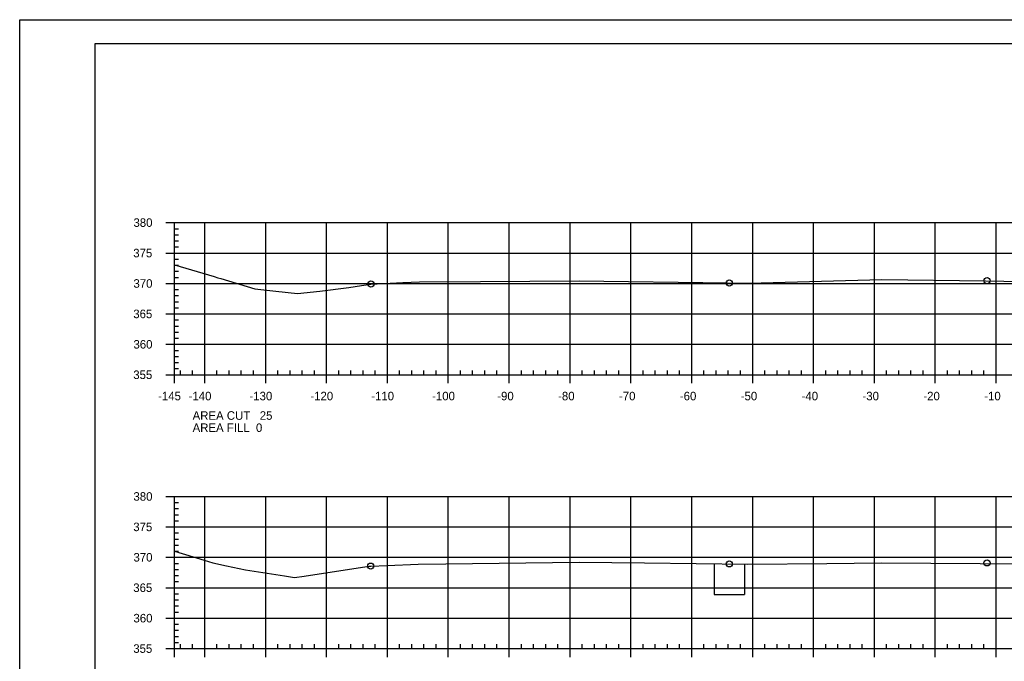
# Model space of a CAD drawing. Extents: x 1359801 to 1362404, y 372415 to 374228.
# Drawn here: x 1360417.1 to 1360578.9, y 373695.8 to 373801.3 of the extents above; entities that cross this region are included whole.
import ezdxf

# ---------------------------------------------------------------- set-up
doc = ezdxf.new("R2010")
doc.units = 0
for name, color, linetype in [('S_DRG_PT_SYM', 7, 'Continuous'), ('S_MAILBOX', 7, 'Continuous'), ('S_PRIMARY_CTL', 7, 'Continuous'), ('S_SHOULDER', 7, 'Continuous'), ('S_UTILITY_POLE_ANNOT', 7, 'Continuous'), ('S_UTL_PT_SYM', 7, 'Continuous'), ('S_WATER_UTILITIES', 7, 'Continuous')]:
    doc.layers.add(name, color=color, linetype=linetype)

msp = doc.modelspace()

# ---------------------------------------------------------------- linework, layer by layer
at = {"layer": 'S_DRG_PT_SYM'}
for points in [[(1360442.53, 373760.99), (1360449.09, 373759.06), (1360449.67, 373758.89), (1360450.14, 373758.75), (1360455.76, 373757.05), (1360459.18, 373756.69), (1360462.78, 373756.29), (1360466.4, 373756.67), (1360471.17, 373757.27), (1360473.27, 373757.6), (1360474.82, 373757.85), (1360480.08, 373758.08), (1360482.79, 373758.2), (1360492.83, 373758.27), (1360509.02, 373758.38), (1360533.39, 373758.02), (1360536.78, 373757.97), (1360538.91, 373758.03), (1360558.72, 373758.6), (1360575.78, 373758.36), (1360584.86, 373758.23)], [(1360442.53, 373713.97), (1360447.4, 373712.49), (1360448.84, 373712.04), (1360451.11, 373711.56), (1360454.2, 373710.87), (1360460.61, 373709.87), (1360462.26, 373709.61), (1360463.85, 373709.86), (1360471.31, 373711), (1360474.52, 373711.46), (1360474.8, 373711.5), (1360477.49, 373711.61), (1360482.57, 373711.82), (1360487.1, 373711.88), (1360509.01, 373712.14), (1360519.76, 373712.02), (1360536.71, 373711.82), (1360549.71, 373711.92), (1360558.67, 373712.03), (1360574.88, 373711.91), (1360584.99, 373711.84)]]:
    msp.add_lwpolyline(points, dxfattribs=at)
at = {"layer": 'S_MAILBOX'}
for p, q in [((1360442.53, 373767.94), (1360732.53, 373767.94)), ((1360442.53, 373742.94), (1360442.53, 373767.94)), ((1360447.53, 373742.94), (1360447.53, 373767.94)), ((1360457.53, 373742.94), (1360457.53, 373767.94)), ((1360467.53, 373742.94), (1360467.53, 373767.94)), ((1360477.53, 373742.94), (1360477.53, 373767.94)), ((1360487.53, 373742.94), (1360487.53, 373767.94)), ((1360497.53, 373742.94), (1360497.53, 373767.94)), ((1360507.53, 373742.94), (1360507.53, 373767.94)), ((1360517.53, 373742.94), (1360517.53, 373767.94)), ((1360527.53, 373742.94), (1360527.53, 373767.94)), ((1360537.53, 373742.94), (1360537.53, 373767.94)), ((1360547.53, 373742.94), (1360547.53, 373767.94)), ((1360557.53, 373742.94), (1360557.53, 373767.94)), ((1360567.53, 373742.94), (1360567.53, 373767.94)), ((1360577.53, 373742.94), (1360577.53, 373767.94)), ((1360442.53, 373762.94), (1360732.53, 373762.94)), ((1360442.53, 373757.94), (1360732.53, 373757.94)), ((1360442.53, 373752.94), (1360732.53, 373752.94)), ((1360442.53, 373747.94), (1360732.53, 373747.94)), ((1360442.53, 373742.94), (1360732.53, 373742.94)), ((1360442.53, 373722.94), (1360732.53, 373722.94)), ((1360442.53, 373697.94), (1360442.53, 373722.94)), ((1360447.53, 373697.94), (1360447.53, 373722.94)), ((1360457.53, 373697.94), (1360457.53, 373722.94)), ((1360467.53, 373697.94), (1360467.53, 373722.94)), ((1360477.53, 373697.94), (1360477.53, 373722.94)), ((1360487.53, 373697.94), (1360487.53, 373722.94)), ((1360497.53, 373697.94), (1360497.53, 373722.94)), ((1360507.53, 373697.94), (1360507.53, 373722.94)), ((1360517.53, 373697.94), (1360517.53, 373722.94)), ((1360527.53, 373697.94), (1360527.53, 373722.94)), ((1360537.53, 373697.94), (1360537.53, 373722.94)), ((1360547.53, 373697.94), (1360547.53, 373722.94)), ((1360557.53, 373697.94), (1360557.53, 373722.94)), ((1360567.53, 373697.94), (1360567.53, 373722.94)), ((1360577.53, 373697.94), (1360577.53, 373722.94)), ((1360442.53, 373717.94), (1360732.53, 373717.94)), ((1360442.53, 373712.94), (1360732.53, 373712.94)), ((1360442.53, 373707.94), (1360732.53, 373707.94)), ((1360442.53, 373702.94), (1360732.53, 373702.94)), ((1360442.53, 373697.94), (1360732.53, 373697.94))]:
    msp.add_line(p, q, dxfattribs=at)
at = {"layer": 'S_SHOULDER'}
msp.add_line((1360417.13, 373801.29), (1360750.46, 373801.29), dxfattribs=at)
for points in [[(1360417.12, 373801.29), (1360750.46, 373801.29), (1360750.46, 373587.95), (1360417.12, 373587.95)], [(1360663.45, 373797.4), (1360663.45, 373787.52), (1360699.18, 373787.52), (1360699.18, 373784.6), (1360722.38, 373784.6), (1360722.38, 373760.26), (1360745.71, 373760.26), (1360745.71, 373591.94), (1360429.53, 373591.94), (1360429.53, 373797.4)]]:
    msp.add_lwpolyline(points, close=True, dxfattribs=at)
for centre in [(1360474.82, 373757.85), (1360533.68, 373758.02), (1360576.03, 373758.4), (1360576.03, 373712.02), (1360474.8, 373711.5), (1360533.68, 373711.85)]:
    msp.add_circle(centre, 0.5, dxfattribs=at)
at = {"layer": 'S_UTILITY_POLE_ANNOT'}
for p, q in [((1360531.19, 373711.85), (1360531.19, 373706.82)), ((1360536.19, 373711.85), (1360536.19, 373706.82)), ((1360531.19, 373706.82), (1360536.19, 373706.82))]:
    msp.add_line(p, q, dxfattribs=at)
at = {"layer": 'S_UTL_PT_SYM'}
for p, q in [((1360429.53, 373797.4), (1360745.71, 373797.4)), ((1360429.53, 373591.94), (1360429.53, 373797.4))]:
    msp.add_line(p, q, dxfattribs=at)
at = {"layer": 'S_WATER_UTILITIES'}
for p, q in [((1360441.13, 373767.94), (1360442.53, 373767.94)), ((1360442.53, 373742.94), (1360442.53, 373767.94)), ((1360442.53, 373766.94), (1360443.23, 373766.94)), ((1360442.53, 373765.94), (1360443.23, 373765.94)), ((1360442.53, 373764.94), (1360443.23, 373764.94)), ((1360441.13, 373762.94), (1360442.53, 373762.94)), ((1360442.53, 373763.94), (1360443.23, 373763.94)), ((1360442.53, 373761.94), (1360443.23, 373761.94)), ((1360442.53, 373760.94), (1360443.23, 373760.94)), ((1360442.53, 373759.94), (1360443.23, 373759.94)), ((1360441.13, 373757.94), (1360442.53, 373757.94)), ((1360442.53, 373758.94), (1360443.23, 373758.94)), ((1360442.53, 373756.94), (1360443.23, 373756.94)), ((1360442.53, 373755.94), (1360443.23, 373755.94)), ((1360442.53, 373754.94), (1360443.23, 373754.94)), ((1360441.13, 373752.94), (1360442.53, 373752.94)), ((1360442.53, 373753.94), (1360443.23, 373753.94)), ((1360442.53, 373751.94), (1360443.23, 373751.94)), ((1360442.53, 373750.94), (1360443.23, 373750.94)), ((1360442.53, 373749.94), (1360443.23, 373749.94)), ((1360442.53, 373748.94), (1360443.23, 373748.94)), ((1360441.13, 373747.94), (1360442.53, 373747.94)), ((1360442.53, 373746.94), (1360443.23, 373746.94)), ((1360442.53, 373745.94), (1360443.23, 373745.94)), ((1360442.53, 373744.94), (1360443.23, 373744.94)), ((1360442.53, 373743.94), (1360443.23, 373743.94)), ((1360442.53, 373742.94), (1360442.53, 373743.64)), ((1360443.53, 373742.94), (1360443.53, 373743.64)), ((1360445.53, 373742.94), (1360445.53, 373743.64)), ((1360449.53, 373742.94), (1360449.53, 373743.64)), ((1360451.53, 373742.94), (1360451.53, 373743.64)), ((1360453.53, 373742.94), (1360453.53, 373743.64)), ((1360455.53, 373742.94), (1360455.53, 373743.64)), ((1360459.53, 373742.94), (1360459.53, 373743.64)), ((1360461.53, 373742.94), (1360461.53, 373743.64)), ((1360463.53, 373742.94), (1360463.53, 373743.64)), ((1360465.53, 373742.94), (1360465.53, 373743.64)), ((1360469.53, 373742.94), (1360469.53, 373743.64)), ((1360471.53, 373742.94), (1360471.53, 373743.64)), ((1360473.53, 373742.94), (1360473.53, 373743.64)), ((1360475.53, 373742.94), (1360475.53, 373743.64)), ((1360479.53, 373742.94), (1360479.53, 373743.64)), ((1360481.53, 373742.94), (1360481.53, 373743.64)), ((1360483.53, 373742.94), (1360483.53, 373743.64)), ((1360485.53, 373742.94), (1360485.53, 373743.64)), ((1360489.53, 373742.94), (1360489.53, 373743.64)), ((1360491.53, 373742.94), (1360491.53, 373743.64)), ((1360493.53, 373742.94), (1360493.53, 373743.64)), ((1360495.53, 373742.94), (1360495.53, 373743.64)), ((1360499.53, 373742.94), (1360499.53, 373743.64)), ((1360501.53, 373742.94), (1360501.53, 373743.64)), ((1360503.53, 373742.94), (1360503.53, 373743.64)), ((1360505.53, 373742.94), (1360505.53, 373743.64)), ((1360509.53, 373742.94), (1360509.53, 373743.64)), ((1360511.53, 373742.94), (1360511.53, 373743.64)), ((1360513.53, 373742.94), (1360513.53, 373743.64)), ((1360515.53, 373742.94), (1360515.53, 373743.64)), ((1360519.53, 373742.94), (1360519.53, 373743.64)), ((1360521.53, 373742.94), (1360521.53, 373743.64)), ((1360523.53, 373742.94), (1360523.53, 373743.64)), ((1360525.53, 373742.94), (1360525.53, 373743.64)), ((1360529.53, 373742.94), (1360529.53, 373743.64)), ((1360531.53, 373742.94), (1360531.53, 373743.64)), ((1360533.53, 373742.94), (1360533.53, 373743.64)), ((1360535.53, 373742.94), (1360535.53, 373743.64)), ((1360539.53, 373742.94), (1360539.53, 373743.64)), ((1360541.53, 373742.94), (1360541.53, 373743.64)), ((1360543.53, 373742.94), (1360543.53, 373743.64)), ((1360545.53, 373742.94), (1360545.53, 373743.64)), ((1360549.53, 373742.94), (1360549.53, 373743.64)), ((1360551.53, 373742.94), (1360551.53, 373743.64)), ((1360553.53, 373742.94), (1360553.53, 373743.64)), ((1360555.53, 373742.94), (1360555.53, 373743.64)), ((1360559.53, 373742.94), (1360559.53, 373743.64)), ((1360561.53, 373742.94), (1360561.53, 373743.64)), ((1360563.53, 373742.94), (1360563.53, 373743.64)), ((1360565.53, 373742.94), (1360565.53, 373743.64)), ((1360569.53, 373742.94), (1360569.53, 373743.64)), ((1360571.53, 373742.94), (1360571.53, 373743.64)), ((1360573.53, 373742.94), (1360573.53, 373743.64)), ((1360575.53, 373742.94), (1360575.53, 373743.64)), ((1360441.13, 373742.94), (1360442.53, 373742.94)), ((1360442.53, 373742.94), (1360732.53, 373742.94)), ((1360442.53, 373741.54), (1360442.53, 373742.94)), ((1360447.53, 373741.54), (1360447.53, 373742.94)), ((1360457.53, 373741.54), (1360457.53, 373742.94)), ((1360467.53, 373741.54), (1360467.53, 373742.94)), ((1360477.53, 373741.54), (1360477.53, 373742.94)), ((1360487.53, 373741.54), (1360487.53, 373742.94)), ((1360497.53, 373741.54), (1360497.53, 373742.94)), ((1360507.53, 373741.54), (1360507.53, 373742.94)), ((1360517.53, 373741.54), (1360517.53, 373742.94)), ((1360527.53, 373741.54), (1360527.53, 373742.94)), ((1360537.53, 373741.54), (1360537.53, 373742.94)), ((1360547.53, 373741.54), (1360547.53, 373742.94)), ((1360557.53, 373741.54), (1360557.53, 373742.94)), ((1360567.53, 373741.54), (1360567.53, 373742.94)), ((1360577.53, 373741.54), (1360577.53, 373742.94)), ((1360441.13, 373722.94), (1360442.53, 373722.94)), ((1360442.53, 373697.94), (1360442.53, 373722.94)), ((1360442.53, 373721.94), (1360443.23, 373721.94)), ((1360442.53, 373720.94), (1360443.23, 373720.94)), ((1360442.53, 373719.94), (1360443.23, 373719.94)), ((1360442.53, 373718.94), (1360443.23, 373718.94)), ((1360441.13, 373717.94), (1360442.53, 373717.94)), ((1360442.53, 373716.94), (1360443.23, 373716.94)), ((1360442.53, 373715.94), (1360443.23, 373715.94)), ((1360442.53, 373714.94), (1360443.23, 373714.94)), ((1360441.13, 373712.94), (1360442.53, 373712.94)), ((1360442.53, 373713.94), (1360443.23, 373713.94)), ((1360442.53, 373711.94), (1360443.23, 373711.94)), ((1360442.53, 373710.94), (1360443.23, 373710.94)), ((1360442.53, 373709.94), (1360443.23, 373709.94)), ((1360441.13, 373707.94), (1360442.53, 373707.94)), ((1360442.53, 373708.94), (1360443.23, 373708.94)), ((1360442.53, 373706.94), (1360443.23, 373706.94)), ((1360442.53, 373705.94), (1360443.23, 373705.94)), ((1360442.53, 373704.94), (1360443.23, 373704.94)), ((1360441.13, 373702.94), (1360442.53, 373702.94)), ((1360442.53, 373703.94), (1360443.23, 373703.94)), ((1360442.53, 373701.94), (1360443.23, 373701.94)), ((1360442.53, 373700.94), (1360443.23, 373700.94)), ((1360442.53, 373699.94), (1360443.23, 373699.94)), ((1360441.13, 373697.94), (1360442.53, 373697.94)), ((1360442.53, 373698.94), (1360443.23, 373698.94)), ((1360442.53, 373697.94), (1360442.53, 373698.64)), ((1360442.53, 373697.94), (1360732.53, 373697.94)), ((1360442.53, 373696.54), (1360442.53, 373697.94)), ((1360443.53, 373697.94), (1360443.53, 373698.64)), ((1360445.53, 373697.94), (1360445.53, 373698.64)), ((1360447.53, 373696.54), (1360447.53, 373697.94)), ((1360449.53, 373697.94), (1360449.53, 373698.64)), ((1360451.53, 373697.94), (1360451.53, 373698.64)), ((1360453.53, 373697.94), (1360453.53, 373698.64)), ((1360455.53, 373697.94), (1360455.53, 373698.64)), ((1360457.53, 373696.54), (1360457.53, 373697.94)), ((1360459.53, 373697.94), (1360459.53, 373698.64)), ((1360461.53, 373697.94), (1360461.53, 373698.64)), ((1360463.53, 373697.94), (1360463.53, 373698.64)), ((1360465.53, 373697.94), (1360465.53, 373698.64)), ((1360467.53, 373696.54), (1360467.53, 373697.94)), ((1360469.53, 373697.94), (1360469.53, 373698.64)), ((1360471.53, 373697.94), (1360471.53, 373698.64)), ((1360473.53, 373697.94), (1360473.53, 373698.64)), ((1360475.53, 373697.94), (1360475.53, 373698.64)), ((1360477.53, 373696.54), (1360477.53, 373697.94)), ((1360479.53, 373697.94), (1360479.53, 373698.64)), ((1360481.53, 373697.94), (1360481.53, 373698.64)), ((1360483.53, 373697.94), (1360483.53, 373698.64)), ((1360485.53, 373697.94), (1360485.53, 373698.64)), ((1360487.53, 373696.54), (1360487.53, 373697.94)), ((1360489.53, 373697.94), (1360489.53, 373698.64)), ((1360491.53, 373697.94), (1360491.53, 373698.64)), ((1360493.53, 373697.94), (1360493.53, 373698.64)), ((1360495.53, 373697.94), (1360495.53, 373698.64)), ((1360497.53, 373696.54), (1360497.53, 373697.94)), ((1360499.53, 373697.94), (1360499.53, 373698.64)), ((1360501.53, 373697.94), (1360501.53, 373698.64)), ((1360503.53, 373697.94), (1360503.53, 373698.64)), ((1360505.53, 373697.94), (1360505.53, 373698.64)), ((1360507.53, 373696.54), (1360507.53, 373697.94)), ((1360509.53, 373697.94), (1360509.53, 373698.64)), ((1360511.53, 373697.94), (1360511.53, 373698.64)), ((1360513.53, 373697.94), (1360513.53, 373698.64)), ((1360515.53, 373697.94), (1360515.53, 373698.64)), ((1360517.53, 373696.54), (1360517.53, 373697.94)), ((1360519.53, 373697.94), (1360519.53, 373698.64)), ((1360521.53, 373697.94), (1360521.53, 373698.64)), ((1360523.53, 373697.94), (1360523.53, 373698.64)), ((1360525.53, 373697.94), (1360525.53, 373698.64)), ((1360527.53, 373696.54), (1360527.53, 373697.94)), ((1360529.53, 373697.94), (1360529.53, 373698.64)), ((1360531.53, 373697.94), (1360531.53, 373698.64)), ((1360533.53, 373697.94), (1360533.53, 373698.64)), ((1360535.53, 373697.94), (1360535.53, 373698.64)), ((1360537.53, 373696.54), (1360537.53, 373697.94)), ((1360539.53, 373697.94), (1360539.53, 373698.64)), ((1360541.53, 373697.94), (1360541.53, 373698.64)), ((1360543.53, 373697.94), (1360543.53, 373698.64)), ((1360545.53, 373697.94), (1360545.53, 373698.64)), ((1360547.53, 373696.54), (1360547.53, 373697.94)), ((1360549.53, 373697.94), (1360549.53, 373698.64)), ((1360551.53, 373697.94), (1360551.53, 373698.64)), ((1360553.53, 373697.94), (1360553.53, 373698.64)), ((1360555.53, 373697.94), (1360555.53, 373698.64)), ((1360557.53, 373696.54), (1360557.53, 373697.94)), ((1360559.53, 373697.94), (1360559.53, 373698.64)), ((1360561.53, 373697.94), (1360561.53, 373698.64)), ((1360563.53, 373697.94), (1360563.53, 373698.64)), ((1360565.53, 373697.94), (1360565.53, 373698.64)), ((1360567.53, 373696.54), (1360567.53, 373697.94)), ((1360569.53, 373697.94), (1360569.53, 373698.64)), ((1360571.53, 373697.94), (1360571.53, 373698.64)), ((1360573.53, 373697.94), (1360573.53, 373698.64)), ((1360575.53, 373697.94), (1360575.53, 373698.64)), ((1360577.53, 373696.54), (1360577.53, 373697.94))]:
    msp.add_line(p, q, dxfattribs=at)

# ---------------------------------------------------------------- texts
at = {"layer": 'S_PRIMARY_CTL'}
for s, p in [('380', (1360435.81, 373767.24)), ('375', (1360435.78, 373762.24)), ('370', (1360435.81, 373757.24)), ('365', (1360435.78, 373752.24)), ('360', (1360435.81, 373747.24)), ('355', (1360435.78, 373742.24)), ('-145', (1360439.86, 373738.74)), ('-140', (1360444.87, 373738.74)), ('-130', (1360454.87, 373738.74)), ('-120', (1360464.87, 373738.74)), ('-110', (1360474.87, 373738.74)), ('-100', (1360484.87, 373738.74)), ('-90', (1360495.57, 373738.74)), ('-80', (1360505.57, 373738.74)), ('-70', (1360515.57, 373738.74)), ('-60', (1360525.57, 373738.74)), ('-50', (1360535.57, 373738.74)), ('-40', (1360545.57, 373738.74)), ('-30', (1360555.57, 373738.74)), ('-20', (1360565.57, 373738.74)), ('-10', (1360575.57, 373738.74)), ('AREA CUT   25', (1360445.53, 373735.54)), ('AREA FILL  0', (1360445.53, 373733.54)), ('380', (1360435.81, 373722.24)), ('375', (1360435.78, 373717.24)), ('370', (1360435.81, 373712.24)), ('365', (1360435.78, 373707.24)), ('360', (1360435.81, 373702.24)), ('355', (1360435.78, 373697.24))]:
    msp.add_text(s, height=1.4, dxfattribs=at).set_placement(p)
at = {"layer": 'S_SHOULDER'}
for p in [(1360482.75, 373758.15), (1360482.53, 373711.77)]:
    msp.add_text('+', height=0.1, dxfattribs=at).set_placement(p)

doc.saveas('drawing.dxf')
